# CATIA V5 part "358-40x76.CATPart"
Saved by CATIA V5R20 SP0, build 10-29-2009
Part number: 358-40X76
Definition: NONE
Nomenclature: 358-40X76
Source: Unknown
Description: 358-40X76
Bounding box of the stored display mesh (mm): x -18 to 58, y -26 to 26, z -26 to 26
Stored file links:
  C:\Users\Utente\Desktop\IO LAVORO\3D X SITO CF\X SITO\PLASTICA\358\358-40x76.CATPart
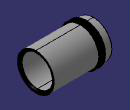
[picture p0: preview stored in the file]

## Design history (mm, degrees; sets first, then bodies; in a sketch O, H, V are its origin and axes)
Body1 "358-40X76" (main body)
  Solid1: solid without history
